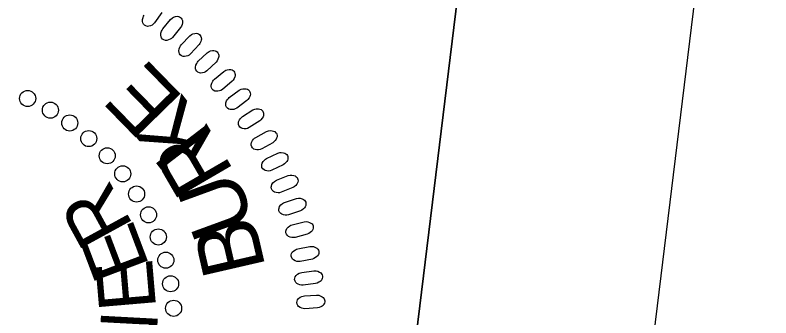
# Model space of a CAD drawing. Extents: x 480344 to 482186, y 489602 to 491961.
# Drawn here: x 481131.1 to 481206.4, y 491879.5 to 491909.7 of the extents above; entities that cross this region are included whole.
import ezdxf

# ---------------------------------------------------------------- set-up
doc = ezdxf.new("R2010")
doc.units = 0
for name, color, linetype in [('Sheet PE Seal Cell', 7, 'Continuous'), ('Sheet Plan CELL', 7, 'Continuous'), ('Sheet Sticker Exception Certification CELL', 7, 'Continuous')]:
    doc.layers.add(name, color=color, linetype=linetype)

msp = doc.modelspace()

# ---------------------------------------------------------------- linework, layer by layer
at = {"layer": 'Sheet PE Seal Cell'}
msp.add_lwpolyline([(481145.72, 491909.939), (481144.991, 491908.914), (481144.874, 491908.79), (481144.755, 491908.703), (481144.59, 491908.626), (481144.417, 491908.578), (481144.291, 491908.571), (481144.129, 491908.613), (481143.996, 491908.685), (481143.898, 491908.805), (481143.843, 491908.907), (481143.797, 491909.062), (481143.799, 491909.268), (481143.85, 491909.454), (481143.901, 491909.577), (481143.965, 491909.69)], dxfattribs=at)
for points in [[(481145.824, 491908.318), (481146.602, 491909.267), (481146.771, 491909.412), (481146.899, 491909.487), (481147.094, 491909.547), (481147.239, 491909.57), (481147.376, 491909.561), (481147.482, 491909.525), (481147.581, 491909.469), (481147.655, 491909.383), (481147.729, 491909.284), (481147.772, 491909.171), (481147.789, 491909.027), (481147.785, 491908.928), (481147.742, 491908.769), (481147.674, 491908.593), (481147.591, 491908.455), (481146.799, 491907.479), (481146.674, 491907.363), (481146.55, 491907.283), (481146.381, 491907.217), (481146.205, 491907.18), (481146.079, 491907.18), (481145.92, 491907.233), (481145.791, 491907.313), (481145.702, 491907.438), (481145.652, 491907.543), (481145.617, 491907.701), (481145.632, 491907.908), (481145.694, 491908.09), (481145.753, 491908.209)], [(481147.66, 491906.723), (481148.496, 491907.62), (481148.673, 491907.755), (481148.806, 491907.822), (481149.004, 491907.87), (481149.15, 491907.884), (481149.287, 491907.866), (481149.39, 491907.824), (481149.486, 491907.762), (481149.554, 491907.671), (481149.622, 491907.567), (481149.657, 491907.452), (481149.665, 491907.308), (481149.655, 491907.208), (481149.603, 491907.053), (481149.524, 491906.881), (481149.432, 491906.749), (481148.581, 491905.825), (481148.448, 491905.716), (481148.32, 491905.645), (481148.146, 491905.589), (481147.969, 491905.563), (481147.843, 491905.571), (481147.687, 491905.634), (481147.565, 491905.722), (481147.483, 491905.852), (481147.44, 491905.96), (481147.414, 491906.12), (481147.442, 491906.325), (481147.516, 491906.503), (481147.583, 491906.618)], [(481149.357, 491905.101), (481150.248, 491905.944), (481150.432, 491906.067), (481150.569, 491906.126), (481150.77, 491906.161), (481150.917, 491906.166), (481151.052, 491906.139), (481151.152, 491906.09), (481151.244, 491906.022), (481151.306, 491905.927), (481151.367, 491905.819), (481151.395, 491905.703), (481151.395, 491905.558), (481151.378, 491905.46), (481151.315, 491905.308), (481151.226, 491905.141), (481151.126, 491905.015), (481150.218, 491904.146), (481150.079, 491904.046), (481149.947, 491903.983), (481149.77, 491903.938), (481149.592, 491903.923), (481149.466, 491903.94), (481149.315, 491904.012), (481149.198, 491904.108), (481149.124, 491904.243), (481149.089, 491904.354), (481149.074, 491904.514), (481149.114, 491904.717), (481149.199, 491904.89), (481149.272, 491905.001)], [(481150.961, 491903.298), (481151.903, 491904.084), (481152.095, 491904.196), (481152.236, 491904.245), (481152.439, 491904.268), (481152.585, 491904.263), (481152.718, 491904.228), (481152.815, 491904.173), (481152.902, 491904.099), (481152.959, 491904.001), (481153.012, 491903.889), (481153.034, 491903.772), (481153.024, 491903.627), (481153.001, 491903.53), (481152.929, 491903.382), (481152.83, 491903.222), (481152.722, 491903.102), (481151.761, 491902.292), (481151.617, 491902.201), (481151.48, 491902.146), (481151.3, 491902.112), (481151.122, 491902.109), (481150.998, 491902.133), (481150.851, 491902.214), (481150.741, 491902.317), (481150.676, 491902.457), (481150.647, 491902.57), (481150.642, 491902.731), (481150.696, 491902.931), (481150.79, 491903.099), (481150.871, 491903.204)], [(481152.447, 491901.493), (481153.436, 491902.218), (481153.636, 491902.317), (481153.779, 491902.358), (481153.982, 491902.367), (481154.128, 491902.354), (481154.259, 491902.31), (481154.353, 491902.25), (481154.435, 491902.17), (481154.485, 491902.069), (481154.532, 491901.954), (481154.546, 491901.835), (481154.527, 491901.691), (481154.498, 491901.596), (481154.417, 491901.453), (481154.307, 491901.299), (481154.192, 491901.187), (481153.182, 491900.438), (481153.032, 491900.356), (481152.893, 491900.31), (481152.712, 491900.288), (481152.533, 491900.295), (481152.411, 491900.327), (481152.27, 491900.418), (481152.165, 491900.527), (481152.11, 491900.671), (481152.088, 491900.785), (481152.093, 491900.947), (481152.159, 491901.143), (481152.264, 491901.304), (481152.351, 491901.404)], [(481153.755, 491899.588), (481154.788, 491900.249), (481154.993, 491900.336), (481155.139, 491900.367), (481155.342, 491900.364), (481155.487, 491900.342), (481155.615, 491900.29), (481155.704, 491900.223), (481155.782, 491900.14), (481155.825, 491900.035), (481155.864, 491899.917), (481155.87, 491899.797), (481155.843, 491899.655), (481155.808, 491899.562), (481155.718, 491899.424), (481155.599, 491899.277), (481155.477, 491899.173), (481154.423, 491898.489), (481154.268, 491898.417), (481154.126, 491898.379), (481153.943, 491898.369), (481153.765, 491898.387), (481153.646, 491898.427), (481153.511, 491898.526), (481153.413, 491898.642), (481153.367, 491898.789), (481153.352, 491898.905), (481153.367, 491899.065), (481153.446, 491899.257), (481153.561, 491899.411), (481153.654, 491899.506)], [(481155.078, 491897.506), (481156.15, 491898.1), (481156.36, 491898.174), (481156.508, 491898.197), (481156.71, 491898.181), (481156.854, 491898.149), (481156.978, 491898.09), (481157.063, 491898.017), (481157.135, 491897.929), (481157.172, 491897.822), (481157.204, 491897.702), (481157.203, 491897.582), (481157.166, 491897.442), (481157.125, 491897.351), (481157.027, 491897.219), (481156.899, 491897.08), (481156.771, 491896.983), (481155.676, 491896.367), (481155.516, 491896.304), (481155.372, 491896.277), (481155.189, 491896.277), (481155.013, 491896.307), (481154.896, 491896.354), (481154.767, 491896.462), (481154.677, 491896.583), (481154.64, 491896.733), (481154.633, 491896.849), (481154.658, 491897.008), (481154.748, 491897.194), (481154.873, 491897.341), (481154.971, 491897.43)], [(481156.161, 491895.415), (481157.269, 491895.941), (481157.483, 491896.002), (481157.631, 491896.015), (481157.833, 491895.986), (481157.974, 491895.946), (481158.094, 491895.878), (481158.175, 491895.802), (481158.241, 491895.708), (481158.271, 491895.599), (481158.295, 491895.478), (481158.286, 491895.358), (481158.241, 491895.22), (481158.195, 491895.132), (481158.088, 491895.007), (481157.952, 491894.875), (481157.818, 491894.787), (481156.686, 491894.241), (481156.523, 491894.189), (481156.378, 491894.169), (481156.195, 491894.182), (481156.021, 491894.223), (481155.907, 491894.277), (481155.785, 491894.393), (481155.703, 491894.52), (481155.675, 491894.672), (481155.675, 491894.787), (481155.71, 491894.945), (481155.813, 491895.125), (481155.946, 491895.264), (481156.05, 491895.346)], [(481157.162, 491893.259), (481158.302, 491893.715), (481158.519, 491893.762), (481158.668, 491893.765), (481158.867, 491893.724), (481159.005, 491893.675), (481159.121, 491893.6), (481159.197, 491893.518), (481159.257, 491893.421), (481159.28, 491893.31), (481159.297, 491893.188), (481159.28, 491893.068), (481159.226, 491892.934), (481159.175, 491892.849), (481159.061, 491892.73), (481158.916, 491892.608), (481158.777, 491892.528), (481157.613, 491892.054), (481157.447, 491892.012), (481157.3, 491892.002), (481157.119, 491892.026), (481156.948, 491892.078), (481156.838, 491892.138), (481156.724, 491892.262), (481156.649, 491892.394), (481156.632, 491892.547), (481156.639, 491892.663), (481156.684, 491892.818), (481156.797, 491892.992), (481156.939, 491893.121), (481157.048, 491893.197)], [(481157.963, 491891.043), (481159.129, 491891.427), (481159.349, 491891.46), (481159.498, 491891.454), (481159.694, 491891.401), (481159.828, 491891.343), (481159.939, 491891.261), (481160.01, 491891.174), (481160.064, 491891.073), (481160.08, 491890.961), (481160.089, 491890.838), (481160.065, 491890.72), (481160.002, 491890.59), (481159.946, 491890.508), (481159.825, 491890.397), (481159.673, 491890.284), (481159.528, 491890.213), (481158.337, 491889.813), (481158.169, 491889.781), (481158.022, 491889.781), (481157.843, 491889.816), (481157.675, 491889.879), (481157.569, 491889.946), (481157.463, 491890.076), (481157.397, 491890.212), (481157.389, 491890.367), (481157.403, 491890.482), (481157.458, 491890.633), (481157.582, 491890.8), (481157.732, 491890.921), (481157.845, 491890.989)], [(481158.705, 491888.809), (481159.892, 491889.119), (481160.114, 491889.138), (481160.262, 491889.123), (481160.455, 491889.057), (481160.585, 491888.991), (481160.691, 491888.902), (481160.756, 491888.811), (481160.804, 491888.707), (481160.812, 491888.594), (481160.813, 491888.471), (481160.782, 491888.354), (481160.712, 491888.228), (481160.65, 491888.15), (481160.522, 491888.047), (481160.363, 491887.944), (481160.215, 491887.882), (481159.001, 491887.558), (481158.831, 491887.537), (481158.685, 491887.545), (481158.508, 491887.591), (481158.344, 491887.664), (481158.242, 491887.739), (481158.144, 491887.875), (481158.088, 491888.016), (481158.089, 491888.169), (481158.111, 491888.284), (481158.175, 491888.432), (481158.309, 491888.59), (481158.466, 491888.701), (481158.583, 491888.762)], [(481159.28, 491886.43), (481160.484, 491886.664), (481160.706, 491886.669), (481160.853, 491886.645), (481161.042, 491886.567), (481161.167, 491886.493), (481161.267, 491886.398), (481161.326, 491886.303), (481161.367, 491886.196), (481161.369, 491886.083), (481161.363, 491885.96), (481161.324, 491885.846), (481161.246, 491885.724), (481161.179, 491885.65), (481161.045, 491885.555), (481160.88, 491885.462), (481160.728, 491885.409), (481159.496, 491885.162), (481159.325, 491885.152), (481159.18, 491885.169), (481159.007, 491885.227), (481158.848, 491885.31), (481158.751, 491885.39), (481158.662, 491885.533), (481158.614, 491885.676), (481158.625, 491885.83), (481158.654, 491885.943), (481158.726, 491886.086), (481158.87, 491886.235), (481159.034, 491886.336), (481159.155, 491886.391)], [(481159.668, 491884.073), (481160.885, 491884.232), (481161.107, 491884.223), (481161.253, 491884.189), (481161.435, 491884.1), (481161.557, 491884.018), (481161.65, 491883.917), (481161.703, 491883.819), (481161.737, 491883.709), (481161.732, 491883.596), (481161.718, 491883.474), (481161.673, 491883.362), (481161.586, 491883.245), (481161.516, 491883.176), (481161.375, 491883.09), (481161.205, 491883.007), (481161.05, 491882.964), (481159.805, 491882.795), (481159.634, 491882.795), (481159.49, 491882.822), (481159.32, 491882.89), (481159.167, 491882.983), (481159.075, 491883.069), (481158.996, 491883.217), (481158.956, 491883.363), (481158.977, 491883.516), (481159.013, 491883.627), (481159.095, 491883.766), (481159.248, 491883.906), (481159.418, 491883.996), (481159.542, 491884.042)], [(481159.925, 491881.739), (481161.15, 491881.82), (481161.37, 491881.798), (481161.513, 491881.756), (481161.69, 491881.655), (481161.806, 491881.565), (481161.894, 491881.458), (481161.94, 491881.357), (481161.967, 491881.246), (481161.954, 491881.133), (481161.933, 491881.012), (481161.88, 491880.903), (481161.788, 491880.792), (481161.712, 491880.727), (481161.567, 491880.65), (481161.392, 491880.578), (481161.234, 491880.545), (481159.981, 491880.454), (481159.811, 491880.465), (481159.668, 491880.501), (481159.503, 491880.58), (481159.356, 491880.682), (481159.27, 491880.774), (481159.2, 491880.926), (481159.17, 491881.075), (481159.2, 491881.226), (481159.243, 491881.334), (481159.334, 491881.468), (481159.495, 491881.598), (481159.67, 491881.678), (481159.797, 491881.716)]]:
    msp.add_lwpolyline(points, close=True, dxfattribs=at)
for centre in [(481132.348, 491901.39), (481134.614, 491900.23), (481136.544, 491898.951), (481138.44, 491897.395), (481140.278, 491895.686), (481141.824, 491893.892), (481143.207, 491891.88), (481144.398, 491889.809), (481145.372, 491887.604), (481146.119, 491885.29), (481146.595, 491882.945), (481146.897, 491880.502)]:
    msp.add_circle(centre, 0.801, dxfattribs=at)
at = {"layer": 'Sheet Plan CELL'}
msp.add_line((481176.581, 491922.827), (481164.469, 491823.563), dxfattribs=at)
msp.add_lwpolyline([(481888.023, 490324.774), (480845.79, 490452.044), (481003.359, 491742.447), (481152.316, 491724.266), (481176.581, 491922.827), (482069.88, 491813.721)], close=True, dxfattribs=at)
at = {"layer": 'Sheet Sticker Exception Certification CELL'}
for p, q in [((481152.316, 491724.266), (481176.568, 491922.828)), ((481152.316, 491724.266), (481176.568, 491922.828)), ((481199.895, 491919.979), (481175.643, 491721.417)), ((481199.895, 491919.979), (481175.643, 491721.417))]:
    msp.add_line(p, q, dxfattribs=at)

# ---------------------------------------------------------------- texts
at = {"layer": 'Sheet PE Seal Cell'}
for s, height, rotation, p in [('E', 6.236, 134.30477, (481148.055, 491901.37)), ('K', 6.236, 127.45912, (481150.992, 491897.581)), ('R', 6.236, 120.18409, (481152.975, 491894.083)), ('R', 5.669, 118.70007, (481142.952, 491888.666)), ('U', 6.236, 110.08424, (481155.028, 491888.892)), ('E', 5.669, 110.76028, (481144.54, 491884.663)), ('B', 6.236, 102.9674, (481156.086, 491884.512)), ('E', 5.669, 94.88068, (481145.161, 491880.487)), ('N', 5.669, 86.94089, (481145.054, 491874.608))]:
    msp.add_text(s, height=height, rotation=rotation, dxfattribs=at).set_placement(p)

doc.saveas('drawing.dxf')
